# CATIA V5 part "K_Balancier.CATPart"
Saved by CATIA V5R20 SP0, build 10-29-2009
Part number: Balancier
Publications: "Point.2"
Bounding box of the stored display mesh (mm): x -58 to -18, y 96.067 to 204.271, z -205.699 to -96.067
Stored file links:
  G:\Khaled_CFAO_2011\ST2M\ST2M_GR2\plakomicki\Khaled\CAD_ThinkMOTION\K_Balancier.CATPart
  G:\Khaled_CFAO_2011\ST2M\ST2M_GR2\plakomicki\Khaled\CAD_ThinkMOTION\K_Jambe.CATProduct
  G:\Khaled_CFAO_2011\ST2M\ST2M_GR2\plakomicki\Khaled\plakomicki\Roue.CATPart
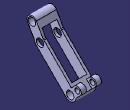
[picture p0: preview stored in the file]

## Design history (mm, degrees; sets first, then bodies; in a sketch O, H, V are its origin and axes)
External parameters (linked from other documents)
  `External.diamètre_essieu` = 15 mm
Set1
  Plane1: linked copy from another document
  Point1 to Point4: linked copy from another document
  Plane2 to Plane4: linked copy from another document
Set2
  Extract1: ExtractElem face of DatumSurface1
  DatumSurface1
  Fill1: Boundary edge of DatumSurface1
  Fill2: Boundary edge of DatumSurface1
Body1 (main body)
  Sketch1 on Plane1, origin (-38, 0, 0), H (0, 1, 0), V (0, 0, 1)
    construction line L1 (106.066, -106.066) -> (122.0244, -134.3503)
    point P1 (106.066, -106.066)
    point P2 (122.0244, -134.3503)
    line L2 (114.7754, -101.1521) -> (130.7338, -129.4363)
    line L3 (113.315, -139.2642) -> (97.3566, -110.98)
    arc A1 centre (122.0244, -134.3503) radius 10 from (130.7338, -129.4363) to (113.315, -139.2642) cw
    arc A2 centre (106.066, -106.066) radius 10 from (97.3566, -110.98) to (114.7754, -101.1521) cw
    reference projected point E1 (106.066, -106.066) from Point1
    reference projected point E2 (122.0244, -134.3503) from Point2
    circle A3 centre (106.066, -106.066) radius 7.5
    point P7 (106.066, -106.066)
    reference projected point E3 (106.066, -106.066) from Point1
    distance L1 L2 = 10
    radius A3 = 7.5
    tangency: A1 L2, A2 L2, A1 L3, A2 L3
    coincidence: P1 E1, P2 E2, E3 P7
  Pad1: profile Sketch1, direction (-1, 0, 0), length 20, mirrored extent
  Sketch2 on Plane1, origin (-38, 0, 0), H (0, 1, 0), V (0, 0, 1)
    construction line L1 (122.0244, -134.3503) -> (182.1285, -194.4544)
    point P1 (122.0244, -134.3503)
    point P2 (182.1285, -194.4544)
    line L2 (129.9793, -126.3953) -> (190.0834, -186.4994)
    line L3 (174.1735, -202.4093) -> (114.0694, -142.3052)
    arc A1 centre (182.1285, -194.4544) radius 11.25 from (190.0834, -186.4994) to (174.1735, -202.4093) cw
    arc A2 centre (122.0244, -134.3503) radius 11.25 from (114.0694, -142.3052) to (129.9793, -126.3953) cw
    reference projected point E1 (122.0244, -134.3503) from Point2
    reference projected point E2 (182.1285, -194.4544) from Point3
    circle A3 centre (182.1285, -194.4544) radius 7.5
    point P7 (182.1285, -194.4544)
    reference projected point E3 (182.1285, -194.4544) from Point3
    distance L1 L2 = 11.25 {= `External.diamètre_essieu`/2 +`External.diamètre_essieu` /4}
    radius A3 = 7.5 {= `External.diamètre_essieu` /2}
    tangency: A1 L2, A2 L2, A1 L3, A2 L3
    coincidence: E1 P1, P2 E2, E3 P7
  Pad2: profile Sketch2, direction (1, 0, 0), length 20, mirrored extent
  Sketch3 on Plane3, origin (0, 7.9792, 7.9792), H (-1, 0, 0), V (0, -0.7071, 0.7071)
    line L1 (23, -165) -> (53, -165)
    line L2 (53, -165) -> (53, -252.6838)
    line L3 (53, -252.6838) -> (23, -252.6838)
    line L4 (23, -252.6838) -> (23, -165)
    reference intersected line E1 through (38, 0) direction (0, -1) from Plane4
    reference projected line E2 through (0, -150) direction (-1, 0) from axis of face of Pad1 from Sketch1.A2
    reference projected line E3 (18, -152.6838) -> (58, -152.6838) from edge [face of Pad1 from Sketch1.L2 | face of Pad1 from Sketch1.A2]
    distance L4 L2 = 30
    distance L2 E1 = 15
    distance E2 L1 = 15
    distance E3 L3 = 100
    horizontal: L1 H, L3 H
    vertical: L2 V, L4 V
  Pocket1: profile Sketch3, direction (0, -0.7071, -0.7071), up to face of Pad2 from Sketch2.L3
  Sketch4 on Plane2, origin (-38, 0, 0), H (0, 1, 0), V (0, 0, 1)
    construction line L1 (196.2706, -180.3122) -> (182.1285, -194.4544)
    point P1 (196.2706, -180.3122)
    point P2 (182.1285, -194.4544)
    line L2 (201.9275, -185.9691) -> (187.7853, -200.1112)
    line L3 (176.4716, -188.7975) -> (190.6137, -174.6554)
    arc A1 centre (182.1285, -194.4544) radius 8 from (187.7853, -200.1112) to (176.4716, -188.7975) cw
    arc A2 centre (196.2706, -180.3122) radius 8 from (190.6137, -174.6554) to (201.9275, -185.9691) cw
    reference projected point E1 (196.2706, -180.3122) from Point4
    reference projected point E2 (182.1285, -194.4544) from Point3
    circle A3 centre (182.1285, -194.4544) radius 7.5
    circle A4 centre (196.2706, -180.3122) radius 5
    point P7 (196.2706, -180.3122)
    reference projected point E3 (196.2706, -180.3122) from Point4
    distance L1 L2 = 8
    radius A3 = 7.5
    radius A4 = 5
    tangency: A1 L2, A2 L2, A1 L3, A2 L3
    coincidence: E1 P1, E2 P2, P7 E3
  Pad3: profile Sketch4, direction (1, 0, 0), length 20, mirrored extent
  Sketch5 on Plane3, origin (0, 7.9792, 7.9792), H (-1, 0, 0), V (0, -0.7071, 0.7071)
    line L1 (28, -256.2843) -> (48, -256.2843)
    line L2 (48, -256.2843) -> (48, -276.2843)
    line L3 (48, -276.2843) -> (28, -276.2843)
    line L4 (28, -276.2843) -> (28, -256.2843)
    reference projected point E1 (38, -266.2843) from Point4
    reference projected point E2 (38, -266.2843) from Point4
    distance L4 L2 = 20
    distance E1 L2 = 10
    distance L1 L3 = 20
    distance L1 E2 = 10
    horizontal: L1 H, L3 H
    vertical: L2 V, L4 V
  Pocket2: profile Sketch5, direction (0, -0.7071, -0.7071), up to face of Pad2 from Sketch2.L2, opposite side length 9
  Sketch6 on face of Pad2, origin (-18, 0, 0), H (0, 1, 0), V (0, 0, 1)
    circle A1 centre (122.0244, -134.3503) radius 7.5
    point P1 (122.0244, -134.3503)
    reference projected point E1 (122.0244, -134.3503) from Point2
    radius A1 = 7.5
    coincidence: P1 E1
  Pocket3: profile Sketch6, direction (-1, 0, 0), up to face of Pad2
